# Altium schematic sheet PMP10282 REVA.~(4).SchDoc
size 431 x 279 mm; Date: Not shown in title block; ApprovedBy: Not shown in title block; CheckedBy: Not shown in title block; Author: Not shown in title block; CompanyName: Not shown in title block; Engineer: Not shown in title block; Organization: Not shown in title block; Address1: Not shown in title block; Address2: Not shown in title block; Address3: Not shown in title block; Address4: Not shown in title block; DocumentNumber: 1; Revision: Use project parameter SCH_Rev; SheetNumber: 1; SheetTotal: 1; PageSetup: Record=PageOptions|CenterHorizontal=True|CenterVertical=True|PrintScale=1.00|XCorrection=1.00|YCorrection=1.00|PrintKind=0|BorderSize=5000000|LeftOffset=0|BottomOffset=0|Orientation=2|PaperLength=1000|PaperWidth=1000|Scale=100|PaperSource=15|PrintQuality=600|MediaType=1|DitherType=10|PaperKind=Letter|PrintScaleMode=1
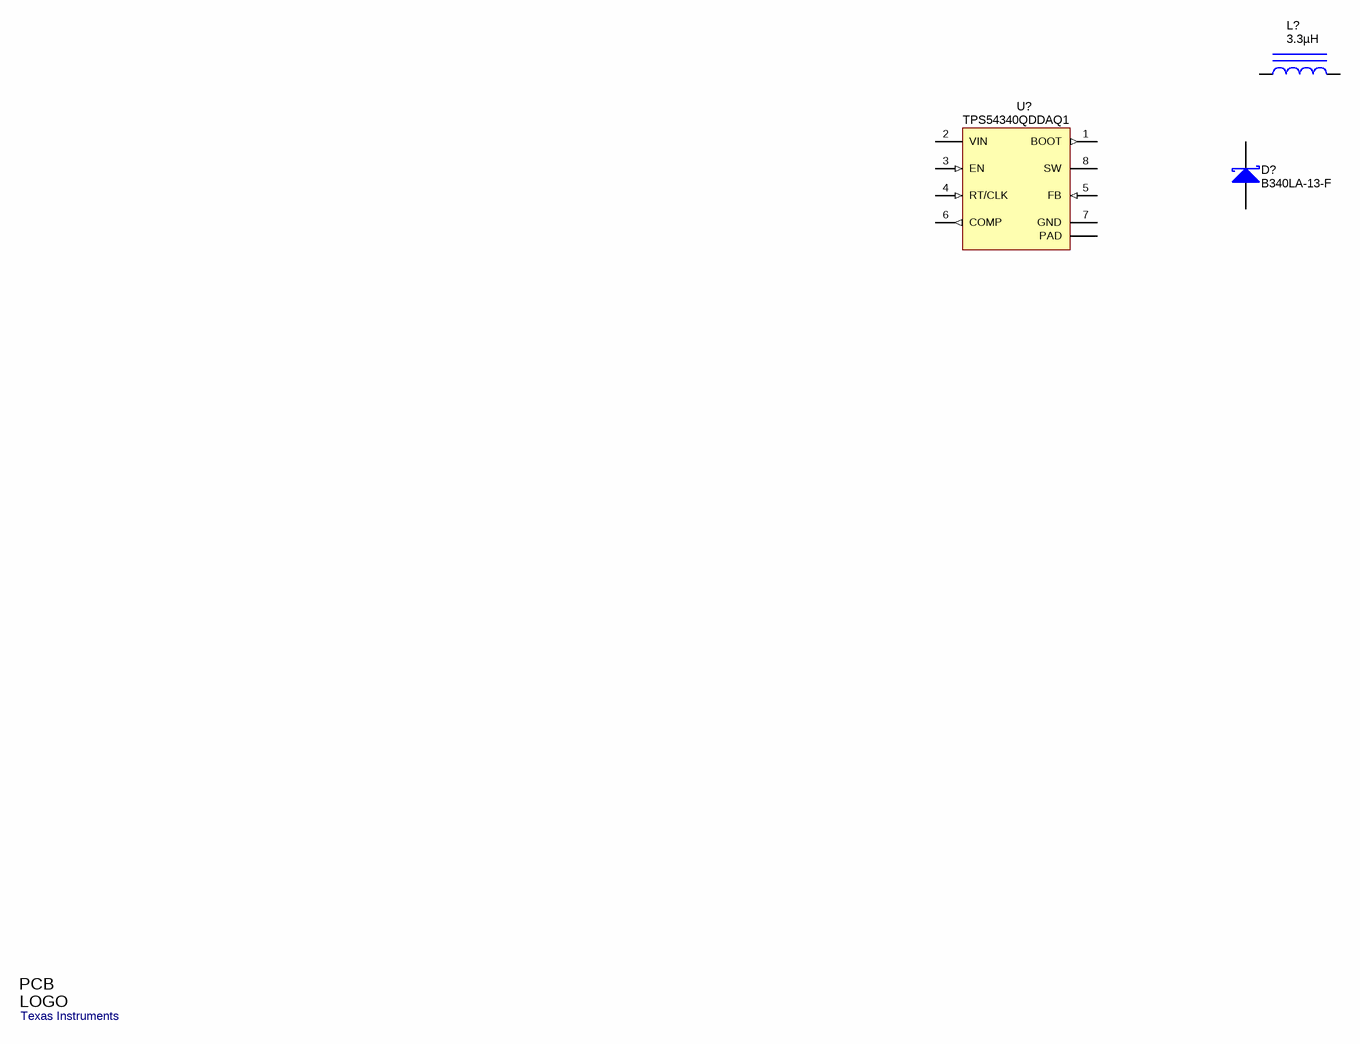
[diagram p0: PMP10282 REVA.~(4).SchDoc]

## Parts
D?  B340LA-13-F  [SMA]
L?  ValueDisplayed: 3.3µH  [SPM6530]  (hidden comment: SPM6530T-3R3M)
Logo1  Texas Instruments  [TI_Stacked_Overlay_Small]  (no BOM)
U?  TPS54340QDDAQ1  [DDA0008E_N]

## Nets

Not connected (* = marked no-connect by the designer): D? 1(K) 2(A); L? 1 2; U? 1(BOOT) 2(VIN) 3(EN) 4(RT/CLK) 5(FB) 6(COMP) 7(GND) 8(SW) 9(PAD)

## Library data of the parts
D? = B340LA-13-F: Diode, Schottky, 40V, 3A, SMA; Manufacturer: Diodes Inc.; U/M: EA; Vf_V: 0.45; Value2: 0.45V; Io_A: 3; Vr_V: 40; TJmax_C: 125; RJC_CperW: 25
L? = SPM6530T-3R3M: Inductor, Shielded, Ferrite, 3.3uH, 6.8A, 0.0297 ohm, SMD; Manufacturer: TDK; Ind_H: 3.3E-6; Imax_A: 6.8; Irms: 6.8A @ 40C rise; Isat: 7.3A @ 20% inductance drop; DCR_ohm: 0.0297
Logo1 = TI_Logo: Texas Instrument Corporate Signature; SymbolCreator: a0412235
U? = TPS54340DDA: 42 V Input, 3.5 A, Step Down DC-DC Converter with Eco-mode, DDA0008E; Alternate Manufacturer: None; Manufacturer: Texas Instruments; SymbolCreator: a0411947; CompType: IC; U/M: EA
